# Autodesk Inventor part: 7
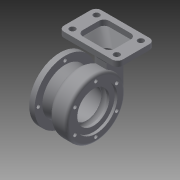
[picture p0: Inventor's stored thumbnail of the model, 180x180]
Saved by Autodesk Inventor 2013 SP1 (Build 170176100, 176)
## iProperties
Created: 2013-05
Part Number: 7
Material: Generic
Document SubType Name: Modeling
Designer: 50384
Density: 1 g/cm^3
Author: 50384
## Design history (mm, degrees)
sketch "Sketch1"
  geometry: L1 (0, 0)-(0, 40); L2 (0, 40)-(-5, 40); L3 (-5, 40)-(-5, 30); L4 (-5, 30)-(-10, 30); L5 (-10, 30)-(-10, 52); L6 (-10, 52)-(-22, 52); L7 (0, 40)-(0, 50); L8 (-5, 55)-(-22, 55); L9 (-37, 40)-(-37, 36.35); L10 (-57.45, 42.99)-(-37, 36.35); L11 (-57.45, 42.99)-(-57.45, 57.49); L12 (-57.45, 57.49)-(-67.45, 57.49); L13 (-67.45, 57.49)-(-67.45, 43.06); L14 (-17.435, 27.47)-(-63.445, 38.16); L15 (-17.435, 27.47)-(-18.622, 27.746); L16 (-17.895, 28.724)-(-34, 35.468); L17 (-34, 35.468)-(-34, 40); L18 (0, 0)-(-62.45, 0); A1 r 5 centre (-5, 50) between (0, 50) and (-5, 55); A2 r 5 centre (-62.45, 43.06) between (-67.45, 43.06) and (-63.445, 38.16); A3 r 1.219 centre (-18.622, 27.746) between (-17.435, 27.47) and (-17.895, 28.724); A4 r 12 centre (-22, 40) between (-22, 52) and (-34, 40); A5 r 15 centre (-22, 40) between (-22, 55) and (-37, 40); 1 further point
  constraints: 36 end point, 10 point on circle, 8 perpendicular, 5 centre point, 4 tangent, 3 parallel, 3 point on line, 2 coincident, 1 vertical
  dimensions: "d7" = 15 distance of L1.end point (0, 55); "d8" = 22 distance of point (0, 55) L8.end; "d9" = 5 radius of A1; "d12" = 3.65 distance of L9.start L9.end; "d15" = 14.5 distance of L10.start L11.end; "d16" = 10 distance of L11.end L12.end; "d17" = 14.43 distance of L13.end L12.end
revolve "Revolution1" sketch "Sketch1" stored, may be unused: angle "d22" = 90 deg
sketch "Sketch2" dims "d23" = 100
  geometry: C1 r 43.06 at (0, 0) reference; C2 r 3.4 at (0, 50); C3 r 3.4 at (-50, 0); C4 r 3.4 at (0, -50); C5 r 3.4 at (50, 0); 1 further point
  constraints: 4 centre point, 1 coincident, 1 vertical alignment, 11 other
  dimensions: "d24" = 6.8 diameter of C2; "d27" = 360 deg dimension on point (0, 0) C2.centre (derived)
extrude "Extrusion1" cut sketch "Sketch2" stored distance "d29" = 25.4; taper "d30" = 0 deg
workplane "Work Plane1"
sketch "Sketch3"
  geometry: L1 (5, 55)-(5, -55) reference; L2 (20, -75)-(75, -75); L3 (65, -75)-(-25, -75); L4 (-35, -65)-(-35, -15); L5 (-25, -5)-(65, -5); L6 (75, -15)-(75, -65); L7 (20, -5)-(20, -15); L8 (20, -15)-(0, -15); L9 (-35, -40)-(-10, -40); L10 (-10, -40)-(-10, -25); L11 (20, -65)-(0, -65); L12 (-10, -40)-(-10, -55); L13 (20, -15)-(40, -15); L14 (50, -40)-(50, -25); L15 (50, -40)-(50, -55); L16 (20, -65)-(40, -65); C1 r 5.5 at (61.46, -17.5); C2 r 5.5 at (61.46, -62.5); C3 r 5.5 at (-21.46, -17.5); C4 r 5.5 at (-21.46, -62.5); A1 r 10 centre (0, -25) between (0, -15) and (-10, -25); A2 r 10 centre (-25, -15) between (-25, -5) and (-35, -15); A3 r 10 centre (-25, -65) between (-35, -65) and (-25, -75); A4 r 10 centre (65, -65) between (65, -75) and (75, -65); A5 r 10 centre (65, -15) between (75, -15) and (65, -5); A6 r 10 centre (0, -55) between (-10, -55) and (0, -65); A7 r 10 centre (40, -25) between (50, -25) and (40, -15); A8 r 10 centre (40, -55) between (40, -65) and (50, -55); 4 further points
  constraints: 30 end point, 16 point on circle, 12 centre point, 11 symmetric about line, 10 tangent, 8 point on line, 4 equal radius, 4 parallel, 3 perpendicular, 2 midpoint, 1 horizontal, 3 other
  dimensions: "d35" = 55 distance of L2.start L2.end; "d36" = 110 distance of point (-35, -5) point (75, -5); "d37" = 70 distance of point (-35, -75) point (-35, -5); "d40" = 11 diameter of C1; "d41" = 10 distance of L7.start L7.end; "d42" = 25 distance of L9.start L9.end; "d43" = 10 radius of A1
extrude "Extrusion2" join sketch "Sketch3" distance "d44" = 10; taper "d45" = 0 deg
workplane "Work Plane2"
sketch "Sketch4"
  geometry: L1 (-10, -55)-(-10, -25) reference; L2 (0, -15)-(40, -15) reference; L3 (50, -25)-(50, -55) reference; L4 (40, -65)-(0, -65) reference; L5 (-35, -15)-(-35, -65) reference; L6 (-25, -75)-(65, -75) reference; L7 (75, -65)-(75, -15) reference; L8 (65, -5)-(-25, -5) reference; L9 (8, -40)-(8, -28); L10 (8, -28)-(20, -28); L11 (8, -52)-(20, -52); L12 (8, -40)-(8, -52); L13 (4, -28)-(4, -55); L14 (20, -24)-(4, -24); L15 (4, -24)-(4, -28); L16 (20, -56)-(4, -56); L17 (4, -56)-(4, -55); C1 r 5.5 at (-21.46, -62.5) reference; C2 r 5.5 at (61.46, -62.5) reference; C3 r 5.5 at (61.46, -17.5) reference; C4 r 5.5 at (-21.46, -17.5) reference; A1 r 10 centre (0, -25) between (0, -15) and (-10, -25) reference; A2 r 10 centre (40, -25) between (50, -25) and (40, -15) reference; A3 r 10 centre (40, -55) between (40, -65) and (50, -55) reference; A4 r 10 centre (0, -55) between (-10, -55) and (0, -65) reference; A5 r 10 centre (-25, -65) between (-35, -65) and (-25, -75) reference; A6 r 10 centre (65, -65) between (65, -75) and (75, -65) reference; A7 r 10 centre (65, -15) between (75, -15) and (65, -5) reference; A8 r 10 centre (-25, -15) between (-25, -5) and (-35, -15) reference; A9 r 12 centre (20, -40) between (20, -52) and (20, -28); A10 r 16 centre (20, -40) between (20, -56) and (20, -24)
  constraints: 18 end point, 4 point on circle, 2 centre point, 2 perpendicular, 2 tangent, 1 coincident, 1 collinear
  dimensions: "d52" = 4 distance of L11.end L16.start
  node "Projected Loop1"
sketch "Sketch5"
  geometry: L1 (10, -25)-(10, -55) reference; L2 (0, -65)-(-40, -65) reference; L3 (-50, -55)-(-50, -25) reference; L4 (-40, -15)-(0, -15) reference; L5 (0, -12.399)-(-40, -12.399); L6 (-52.601, -25)-(-52.601, -55); L7 (-40, -67.601)-(0, -67.601); L8 (12.601, -55)-(12.601, -25); A1 r 10 centre (0, -55) between (0, -65) and (10, -55) reference; A2 r 10 centre (-40, -55) between (-50, -55) and (-40, -65) reference; A3 r 10 centre (-40, -25) between (-40, -15) and (-50, -25) reference; A4 r 10 centre (0, -25) between (10, -25) and (0, -15) reference; A5 r 12.601 centre (-40, -25) between (-40, -12.399) and (-52.601, -25); A6 r 12.601 centre (-40, -55) between (-52.601, -55) and (-40, -67.601); A7 r 12.601 centre (0, -55) between (0, -67.601) and (12.601, -55); A8 r 12.601 centre (0, -25) between (12.601, -25) and (0, -12.399); 1 further point
  constraints: 8 end point, 8 point on circle, 4 centre point, 7 other
loft "Loft1" dims "d53" = 0, "d54" = 90 deg, "d55" = 0, "d56" = 90 deg
loft "Loft2" dims "d57" = 0, "d58" = 90 deg, "d59" = 0, "d60" = 90 deg
sketch "Sketch6"
  geometry: L1 (12, -4)-(12, -19.752) reference; L2 (12, -28)-(0, -28) reference; L3 (0, -4)-(8.616, -4) reference; L4 (16, 0)-(16, -9.102) reference; L5 (0, 0)-(16, 0) reference; L6 (16, -22.898)-(16, -32) reference; L7 (16, -9.102)-(16, -22.898) reference; L8 (-2, -31)-(15, -31) reference; L9 (-2, -31)-(-2, 79) reference; L10 (-17, -16)-(-17, 64) reference; L11 (16, -30.899)-(-8.75, -29.395); A1 r 16 centre (0, -16) between (0, 0) and (-12.469, -5.974) reference; A2 r 16 centre (0, -16) between (-12.469, -5.974) and (-12.469, -26.026) reference; A3 r 16 centre (0, -16) between (-12.469, -26.026) and (0, -32) reference; A4 r 5 centre (15, -26) between (15, -31) and (20, -26) reference; A5 r 15 centre (-2, -16) between (-17, -16) and (-2, -31) reference; 3 further points
  constraints: 3 point on circle, 2 end point, 2 vertical alignment, 1 horizontal alignment, 1 point on line, 2 other
extrude "Extrusion3" join sketch "Sketch6" stored distance "d61" = 127; taper "d62" = 0 deg
sketch "Sketch7"
  geometry: L1 (-20, 28)-(-8, 28) reference; L2 (-8, 28)-(-8, 52) reference; L3 (-8, 52)-(-20, 52) reference; L4 (-22, 51.832)-(-22, 28.168) reference; L5 (-22, 51.832)-(-22, 28.168) reference; L6 (-8.824, 28)-(-8.824, 52); L7 (-32, 40)-(-8, 40); L8 (-10.4, 28)-(-10.4, 52); L9 (-32, 40)-(-8, 40); L10 (-22, 40)-(-10.4, 40); L11 (-10.4, 40)-(-10.4, 52); L12 (-10.4, 52)-(-22, 52); L13 (-22, 52)-(-22, 40); L14 (-10.4, 40.546)-(-8.824, 40.546); L15 (-8.824, 40.546)-(-8.824, 52); L16 (-8.824, 52)-(-10.4, 52); L17 (-10.4, 52)-(-10.4, 40.546); L18 (-10.4, 40)-(-8, 40); L19 (-8, 40)-(-8, 52); L20 (-8, 52)-(-10.4, 52); L21 (-10.4, 52)-(-10.4, 40); L22 (-22, 40)-(-30.84, 34.853); 3 further points
  constraints: 34 end point, 6 parallel, 6 perpendicular, 6 point on line, 3 horizontal, 2 midpoint, 7 other
  node "Projected Loop3"
  node "Projected Loop4"
extrude "Extrusion4" cut sketch "Sketch7" distance "d63" = 63.5; taper "d64" = 0 deg
extrude "Extrusion5" cut sketch "Sketch7" distance "d65" = 88.9; taper "d66" = 0 deg
sketch "Sketch8" dims "d67" = 90
  geometry: C1 r 50 at (0, 0) reference; C2 r 3.4 at (0, 45); C3 r 3.4 at (-38.971, 22.5); C4 r 3.4 at (-38.971, -22.5); C5 r 3.4 at (0, -45); C6 r 3.4 at (38.971, -22.5); C7 r 3.4 at (38.971, 22.5); 1 further point
  constraints: 6 centre point, 1 coincident, 1 vertical alignment, 15 other
  dimensions: "d68" = 6.8 diameter of C2; "d71" = 360 deg dimension on point (0, 0) C2.centre (derived)
extrude "Extrusion6" cut sketch "Sketch8" stored distance "d73" = 88.9; taper "d74" = 0 deg
body "Solid1"
node "Projected Loop2"
